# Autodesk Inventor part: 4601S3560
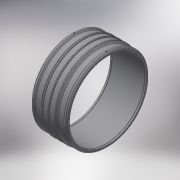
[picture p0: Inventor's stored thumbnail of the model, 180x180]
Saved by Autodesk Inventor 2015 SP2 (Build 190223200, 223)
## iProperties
Created: 2017-06
Part Number: 4601S3560
Material: Generic
Description: PLASSON SUPER LIGHTFIT 560 MM
Document SubType Name: Modeling
Designer: KIM
Mass: 13906.4 g
Surface Area: 12992.7 cm^2
Volume: 13906.4 cm^3
Density: 1 g/cm^3
Appearance: Default
Author: KIM
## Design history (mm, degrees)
derived "4601S3.ipt"
feature "Solid1::4601S3.ipt"
tag "TaggingFeature1"
body "Solid1"
other parameters: "d14" = 17.6296, "d15" = 155, "d16" = 155, "d19" = 3.52592, "d20" = 168 deg, "d24" = 601.4, "d25" = 135 deg, "d26" = 124, "d27" = 135 deg, "d35" = 15, "d39" = 0, "d40" = 4, "d41" = 14, "d42" = 0, "d43" = 135 deg, "d44" = 34.1, "d45" = 12.4, "d46" = 12.4, "d47" = 12.4, "d48" = 607.6, "d50" = 3.1, "d51" = 6, "d52" = 0, "L_1" = 155, "d_2" = 12
